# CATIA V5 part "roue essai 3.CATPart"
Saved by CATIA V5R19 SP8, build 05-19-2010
Part number: roue essai 3
Bounding box of the stored display mesh (mm): x -10.3 to 10.3, y -210 to 210, z -210 to 210
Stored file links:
  G:\EU_thinkMotion\CFAO_2010\SIL_groupe1\SIL_groupe1\A reprendre\scador\monocycle\roue essai 3.CATPart
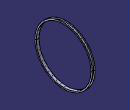
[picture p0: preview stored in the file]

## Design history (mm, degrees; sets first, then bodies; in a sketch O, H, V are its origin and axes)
Parameters
  rayon_roue = 200 mm
Body1 (main body)
  Sketch1 on yz-plane, origin (0, 0, 0), H (0, 1, 0), V (0, 0, 1)
    circle A1 centre (0, 0) radius 200
    radius A1 = 200 {= rayon_roue}
  Sketch2 on zx-plane, origin (0, 0, 0), H (-1, 0, 0), V (0, 0, 1)
    line L1 (-10.3, 200) -> (10.3, 200)
    line L2 (10.3, 200) -> (10.3, 210)
    line L3 (10.3, 210) -> (10, 210)
    point P4 (10, 210)
    line L4 (10, 210) -> (10, 200.3)
    line L5 (10, 200.3) -> (-10, 200.3)
    line L6 (-10, 200.3) -> (-10, 210)
    point P7 (-10, 210)
    line L7 (-10, 210) -> (-10.3, 210)
    line L8 (-10.3, 210) -> (-10.3, 200.3)
    point P9 (-10.3, 200.3)
    line L9 (-10.3, 200.3) -> (-10.3, 200)
    reference projected line E1 (0, -200) -> (0, 200) from Sketch1.A1
    reference projected line E2 (0, -200) -> (0, 200) from Sketch1.A1
    distance L1 H = 200 {= rayon_roue}
    distance L5 L1 = 0.3
    distance L4 L2 = 0.3
    distance L8 L6 = 0.3
    distance E1 L4 = 10
    distance E2 L6 = 10
    distance L1 P4 = 10
    horizontal: L1 H, L3 H, L5 H, L7 H
    vertical: L2 V, L4 V, L6 V, L8 V, L9 V
    coincidence: P7 L3, P9 L5
  Rib1: profile Sketch2, centre curve Sketch1
  Sketch3 on {plane type Tangent, Support face of Rib1, RefPoint {point type OnSurface, Support face of Rib1, RefPoint {point stored without definition}, Length 0, Direction (0, 956.9057, -290.3988)}}, origin (-3.771, 58.1669, 191.6682), H (1, 0, 0), V (0, -0.9569, 0.2904)
    point P1 (3.771, -4.2915)
    reference projected point E1 (3.771, -4.2915) from Sketch4.P8
    coincidence: P1 E1
  Hole1: placed by Sketch3, at (0, 62.2591, 190.3783) direction (0, -0.3108, -0.9505), diameter 2.3, through (limit type 6)
  CircPattern1: of Hole1, instances 41, angular step 9, axis from face of Rib1
  Sketch4 on yz-plane, origin (0, 0, 0), H (0, 1, 0), V (0, 0, 1)
    circle A1 centre (0, 0) radius 200
    point P1 (197.633, 30.6789)
    point P2 (190.3906, 61.2487)
    point P3 (178.4506, 90.3072)
    point P4 (162.1075, 117.1374)
    point P5 (141.7645, 141.0774)
    point P6 (117.9236, 161.5365)
    point P7 (91.1731, 178.0098)
    point P8 (62.1729, 190.0908)
    point P9 (31.6387, 197.4816)
    point P10 (0.3239, 199.9997)
    point P11 (-30.999, 197.5831)
    point P12 (-61.5569, 190.2912)
    point P13 (-90.596, 178.3041)
    point P14 (-117.3998, 161.9175)
    point P15 (-141.3068, 141.5358)
    point P16 (-161.7272, 117.6618)
    point P17 (-178.1572, 90.8847)
    point P18 (-190.1913, 61.865)
    point P19 (-197.5326, 31.3189)
    point P20 (-200, 0)
    point P21 (-197.5326, -31.3189)
    point P22 (-190.1913, -61.865)
    point P23 (-178.1572, -90.8847)
    point P24 (-161.7272, -117.6618)
    point P25 (-141.3068, -141.5358)
    point P26 (-117.3998, -161.9175)
    point P27 (-90.596, -178.3041)
    point P28 (-61.5569, -190.2912)
    point P29 (-30.999, -197.5831)
    point P30 (0.3239, -199.9997)
    point P31 (31.6387, -197.4816)
    point P32 (62.1729, -190.0908)
    point P33 (91.1731, -178.0098)
    point P34 (117.9236, -161.5365)
    point P35 (141.7645, -141.0774)
    point P36 (162.1075, -117.1374)
    point P37 (178.4506, -90.3072)
    point P38 (190.3906, -61.2487)
    point P39 (197.633, -30.6789)
    point P40 (199.999, 0.6478)
    radius A1 = 200 {= rayon_roue}
    distance P1 P2 = 31.4159 {= rayon_roue *2*PI /40}
    distance P2 P3 = 31.4159 {= rayon_roue *2*PI /40}
    distance P3 P4 = 31.4159 {= rayon_roue *2*PI /40}
    distance P4 P5 = 31.4159 {= rayon_roue *2*PI /40}
    distance P5 P6 = 31.4159 {= rayon_roue *2*PI /40}
    distance P6 P7 = 31.4159 {= rayon_roue *2*PI /40}
    distance P7 P8 = 31.4159 {= rayon_roue *2*PI /40}
    distance P8 P9 = 31.4159 {= rayon_roue *2*PI /40}
    distance P9 P10 = 31.4159 {= rayon_roue *2*PI /40}
    distance P10 P11 = 31.4159 {= rayon_roue *2*PI /40}
    distance P11 P12 = 31.4159 {= rayon_roue *2*PI /40}
    distance P12 P13 = 31.4159 {= rayon_roue *2*PI /40}
    distance P13 P14 = 31.4159 {= rayon_roue *2*PI /40}
    distance P14 P15 = 31.4159 {= rayon_roue *2*PI /40}
    distance P15 P16 = 31.4159 {= rayon_roue *2*PI /40}
    distance P16 P17 = 31.4159 {= rayon_roue *2*PI /40}
    distance P17 P18 = 31.4159 {= rayon_roue *2*PI /40}
    distance P18 P19 = 31.4159 {= rayon_roue *2*PI /40}
    distance P19 P20 = 31.4159 {= rayon_roue *2*PI /40}
    distance P20 P21 = 31.4159 {= rayon_roue *2*PI /40}
    distance P21 P22 = 31.4159 {= rayon_roue *2*PI /40}
    distance P22 P23 = 31.4159 {= rayon_roue *2*PI /40}
    distance P23 P24 = 31.4159 {= rayon_roue *2*PI /40}
    distance P24 P25 = 31.4159 {= rayon_roue *2*PI /40}
    distance P25 P26 = 31.4159 {= rayon_roue *2*PI /40}
    distance P26 P27 = 31.4159 {= rayon_roue *2*PI /40}
    distance P27 P28 = 31.4159 {= rayon_roue *2*PI /40}
    distance P28 P29 = 31.4159 {= rayon_roue *2*PI /40}
    distance P29 P30 = 31.4159 {= rayon_roue *2*PI /40}
    distance P30 P31 = 31.4159 {= rayon_roue *2*PI /40}
    distance P31 P32 = 31.4159 {= rayon_roue *2*PI /40}
    distance P32 P33 = 31.4159 {= rayon_roue *2*PI /40}
    distance P33 P34 = 31.4159 {= rayon_roue *2*PI /40}
    distance P34 P35 = 31.4159 {= rayon_roue *2*PI /40}
    distance P35 P36 = 31.4159 {= rayon_roue *2*PI /40}
    distance P36 P37 = 31.4159 {= rayon_roue *2*PI /40}
    distance P37 P38 = 31.4159 {= rayon_roue *2*PI /40}
    distance P38 P39 = 31.4159 {= rayon_roue *2*PI /40}
    distance P39 P40 = 31.4159 {= 2*PI *rayon_roue/40}
    coincidence: A1 P1, A1 P2, A1 P3, A1 P4, A1 P5, A1 P6, A1 P7, A1 P8, A1 P9, A1 P10, A1 P11, A1 P12, A1 P13, A1 P14, A1 P15, A1 P16, A1 P17, A1 P18, A1 P19, A1 P20, A1 P21, A1 P22, A1 P23, A1 P24, A1 P25, A1 P26, A1 P27, A1 P28, A1 P29, A1 P30, A1 P31, A1 P32, A1 P33, A1 P34, A1 P35, A1 P36, A1 P37, A1 P38, A1 P39, A1 P40
Relations
  Sketch4.distance(P1 P2) = Sketch4.distance(P1 P2) (deactivated)
  Sketch4.distance(P39 P40) = PI *2*rayon_roue/40 (deactivated)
